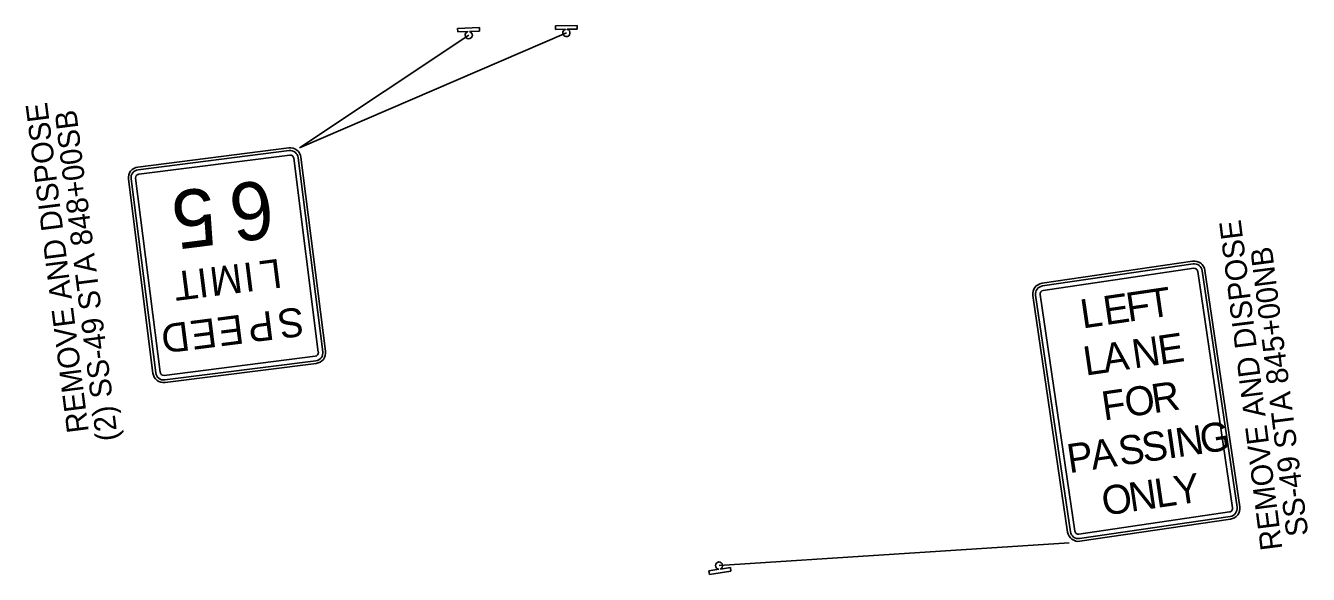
# Model space of a CAD drawing. Extents: x 641128 to 649424, y 422807 to 432853.
# Drawn here: x 643650 to 644358, y 429058 to 429361 of the extents above; entities that cross this region are included whole.
import ezdxf

# ---------------------------------------------------------------- set-up
doc = ezdxf.new("R2010")
doc.units = 0
doc.layers.add('R_Dimension', color=7, linetype='Continuous')
doc.layers.add('S_SIGN', color=7, linetype='Continuous')

msp = doc.modelspace()

# ---------------------------------------------------------------- linework, layer by layer
at = {"layer": 'S_SIGN'}
for p, q in [((643888.21, 429359.4), (643900.2, 429359.82)), ((643900.2, 429359.82), (643900.27, 429357.82)), ((643942.24, 429360.85), (643954.23, 429360.89)), ((643942.24, 429358.85), (643942.24, 429360.85)), ((643954.23, 429360.89), (643954.24, 429358.89)), ((643800.97, 429293.47), (643948.25, 429356.87)), ((643800.97, 429293.47), (643894.34, 429355.61)), ((643888.28, 429357.4), (643888.21, 429359.4)), ((643893.79, 429357.59), (643888.28, 429357.4)), ((643893.79, 429357.53), (643893.79, 429357.59)), ((643900.27, 429357.82), (643894.7, 429357.62)), ((643894.7, 429357.62), (643894.7, 429357.58)), ((643947.76, 429358.87), (643942.24, 429358.85)), ((643947.76, 429358.81), (643947.76, 429358.87)), ((643954.24, 429358.89), (643948.67, 429358.87)), ((643948.67, 429358.87), (643948.67, 429358.83)), ((643795, 429293.36), (643711.66, 429282.8)), ((643815.28, 429181.02), (643801.7, 429288.16)), ((643706.47, 429276.09), (643720.04, 429168.95)), ((644293.94, 429230.82), (644210.83, 429218.61)), ((644319.93, 429095.15), (644300.75, 429225.75)), ((644205.76, 429211.8), (644224.95, 429081.2)), ((643726.75, 429163.75), (643810.08, 429174.31)), ((644231.76, 429076.14), (644314.87, 429088.35)), ((644032.52, 429062.69), (644225.82, 429075.27)), ((644026.89, 429059.82), (644032.4, 429060.65)), ((644027.19, 429057.84), (644026.89, 429059.82)), ((644039.05, 429059.63), (644027.19, 429057.84)), ((644032.4, 429060.65), (644032.39, 429060.7)), ((644033.29, 429060.84), (644033.3, 429060.79)), ((644033.3, 429060.79), (644038.75, 429061.61)), ((644038.75, 429061.61), (644039.05, 429059.63))]:
    msp.add_line(p, q, dxfattribs=at)
for points in [[(643795.19, 429291.87), (643711.85, 429281.31)], [(643712.17, 429278.83), (643795.5, 429289.39)], [(643795.19, 429291.87), (643795.19, 429291.87), (643795.19, 429291.87)], [(643797.74, 429287.66), (643811.31, 429180.51)], [(643813.79, 429180.83), (643800.22, 429287.97)], [(643707.95, 429276.28), (643721.53, 429169.14)], [(643707.95, 429276.28), (643707.95, 429276.28), (643707.95, 429276.28)], [(643724.01, 429169.45), (643710.43, 429276.6)], [(644294.16, 429229.33), (644211.05, 429217.12)], [(644211.41, 429214.65), (644294.52, 429226.86)], [(644294.16, 429229.33), (644294.16, 429229.33), (644294.16, 429229.33)], [(644296.79, 429225.17), (644315.97, 429094.57)], [(644318.45, 429094.94), (644299.26, 429225.53)], [(644207.25, 429212.02), (644226.43, 429081.42)], [(644207.25, 429212.02), (644207.25, 429212.02), (644207.25, 429212.02)], [(644228.91, 429081.78), (644209.72, 429212.38)], [(643809.58, 429178.28), (643726.24, 429167.72)], [(643726.56, 429165.24), (643809.89, 429175.8)], [(643813.79, 429180.83), (643813.79, 429180.83), (643813.79, 429180.83)], [(643726.56, 429165.24), (643726.56, 429165.24), (643726.56, 429165.24)], [(644314.28, 429092.3), (644231.18, 429080.1)], [(644318.45, 429094.94), (644318.45, 429094.94), (644318.45, 429094.94)], [(644231.54, 429077.62), (644314.65, 429089.83)], [(644231.54, 429077.62), (644231.54, 429077.62), (644231.54, 429077.62)]]:
    msp.add_lwpolyline(points, dxfattribs=at)
for centre, radius, start, end in [((643894.34, 429355.61), 2, 182.00281, 79.68291), ((643894.34, 429355.61), 2, 105.86494, 182.00281), ((643948.25, 429356.87), 2, 180.18464, 77.86474), ((643948.25, 429356.87), 2, 104.04677, 180.18464), ((643795.75, 429287.41), 6, 7.2203, 97.22051), ((643795.75, 429287.41), 4.5, 7.2203, 97.22051), ((643795.75, 429287.41), 2, 7.2203, 97.22051), ((643712.42, 429276.85), 6, 97.22051, 187.22072), ((643712.42, 429276.85), 4.5, 97.22051, 187.22072), ((643712.42, 429276.85), 2, 97.22051, 187.22072), ((644294.81, 429224.88), 6, 8.3567, 98.35691), ((644294.81, 429224.88), 4.5, 8.3567, 98.35691), ((644294.81, 429224.88), 2, 8.3567, 98.35691), ((644211.7, 429212.67), 6, 98.35691, 188.35654), ((644211.7, 429212.67), 4.5, 98.35691, 188.35654), ((644211.7, 429212.67), 2, 98.35691, 188.35654), ((643809.33, 429180.26), 2, 277.22066, 7.2203), ((643809.33, 429180.26), 4.5, 277.22066, 7.2203), ((643809.33, 429180.26), 6, 277.22066, 7.2203), ((643725.99, 429169.7), 6, 187.22045, 277.22066), ((643725.99, 429169.7), 4.5, 187.22045, 277.22066), ((643725.99, 429169.7), 2, 187.22045, 277.22066), ((644313.99, 429094.28), 2, 278.35675, 8.35697), ((644313.99, 429094.28), 4.5, 278.35675, 8.35697), ((644313.99, 429094.28), 6, 278.35675, 8.35697), ((644230.89, 429082.07), 6, 188.35654, 278.35675), ((644230.89, 429082.07), 4.5, 188.35654, 278.35675), ((644230.89, 429082.07), 2, 188.35654, 278.35675), ((644032.52, 429062.69), 2, 8.56359, 266.24369), ((644032.52, 429062.69), 2, 292.42572, 8.56359)]:
    msp.add_arc(centre, radius, start, end, dxfattribs=at)

# ---------------------------------------------------------------- texts
at = {"layer": 'R_Dimension'}
for s, p in [('REMOVE AND DISPOSE', (643684.61, 429136.73)), ('(2) SS-49 STA 848+00SB', (643700.73, 429132.15))]:
    msp.add_text(s, height=12, rotation=97.22045, dxfattribs=at).set_placement(p)
at = {"layer": 'S_SIGN'}
for s, height, rotation, p in [('6', 32, 187.22045, (643784.41, 429275.89)), ('5', 32, 187.22045, (643752.57, 429271.85)), ('REMOVE AND DISPOSE', 12, 97.22045, (644343.51, 429071.86)), ('SS-49 STA 845+00NB', 12, 97.22045, (644357.82, 429079.62)), ('T', 16, 187.22045, (643743.51, 429226.36)), ('I', 16, 187.22045, (643749.49, 429227.11)), ('M', 16, 187.22045, (643768.19, 429229.48)), ('I', 16, 187.22045, (643774.98, 429230.34)), ('L', 16, 187.22045, (643789.89, 429232.23)), ('E', 16, 8.3567, (644245.82, 429195.45)), ('F', 16, 8.3567, (644258.43, 429197.3)), ('T', 16, 8.3567, (644270.06, 429199.01)), ('S', 16, 187.22045, (643802.34, 429205.58)), ('L', 16, 8.3567, (644233.2, 429193.59)), ('D', 16, 187.22045, (643739.09, 429197.57)), ('E', 16, 187.22045, (643754, 429199.46)), ('E', 16, 187.22045, (643768.91, 429201.35)), ('P', 16, 187.22045, (643785.62, 429203.47)), ('E', 16, 8.3567, (644276, 429173.6)), ('L', 16, 8.3567, (644234.82, 429167.55)), ('A', 16, 8.3567, (644245.45, 429169.12)), ('N', 16, 8.3567, (644261.65, 429171.5)), ('O', 16, 8.3567, (644257.58, 429144.62)), ('R', 16, 8.3567, (644272.42, 429146.8)), ('F', 16, 8.3567, (644244.96, 429142.76)), ('N', 16, 8.3567, (644285.69, 429122.47)), ('G', 16, 8.3567, (644299.11, 429124.44)), ('S', 16, 8.3567, (644254.15, 429117.84)), ('S', 16, 8.3567, (644267.01, 429119.72)), ('I', 16, 8.3567, (644280.43, 429121.7)), ('P', 16, 8.3567, (644225.83, 429113.68)), ('A', 16, 8.3567, (644238.69, 429115.56)), ('Y', 16, 8.3567, (644284.8, 429096.06)), ('O', 16, 8.3567, (644244.98, 429090.21)), ('N', 16, 8.3567, (644259.82, 429092.39)), ('L', 16, 8.3567, (644274.17, 429094.5))]:
    msp.add_text(s, height=height, rotation=rotation, dxfattribs=at).set_placement(p)

doc.saveas('drawing.dxf')
